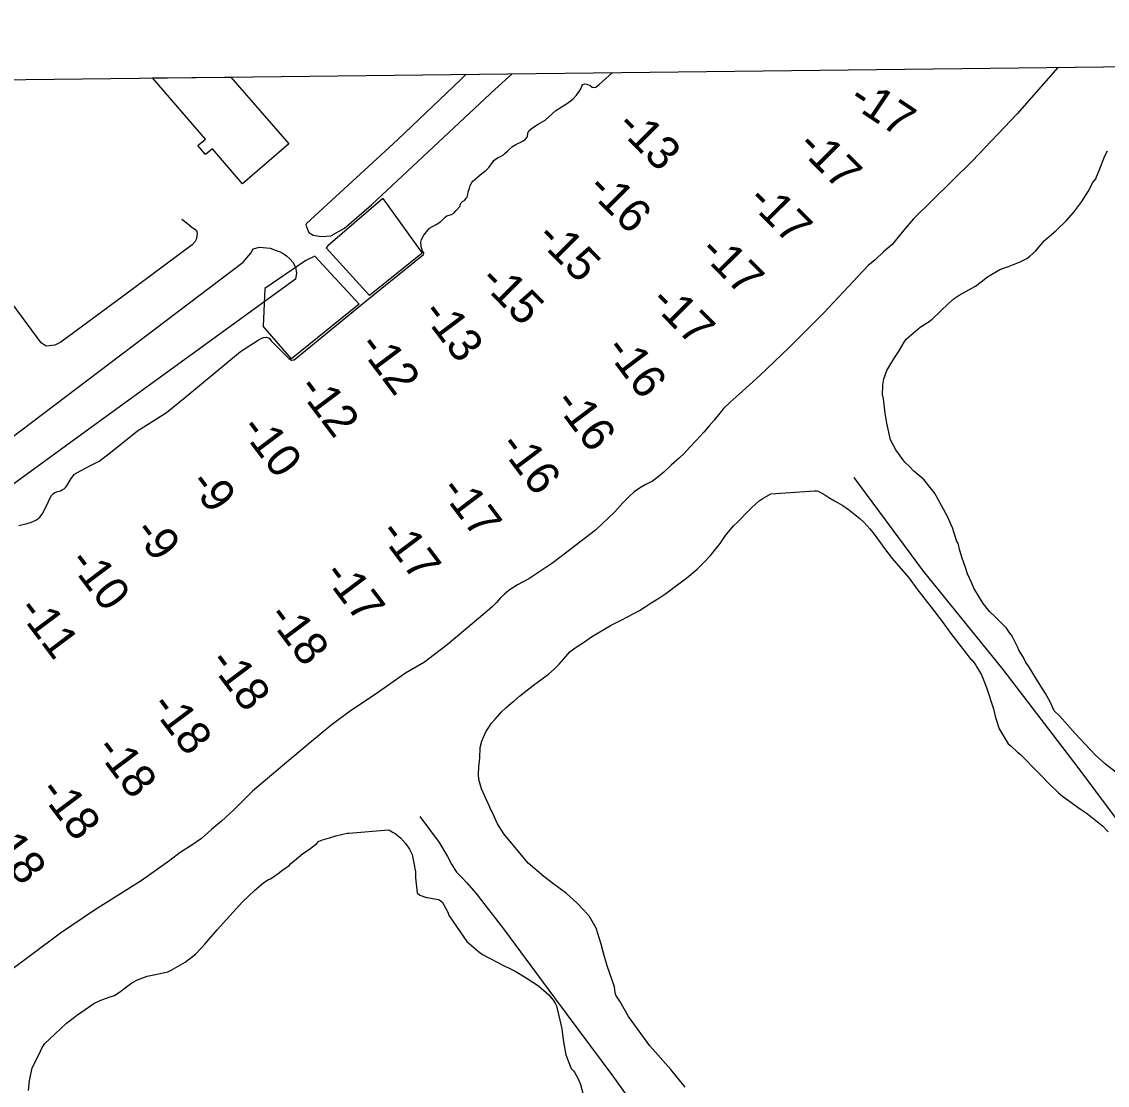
# Model space of a CAD drawing. Extents: x 3683613 to 3738215, y 469626 to 495384.
# Drawn here: x 3695195 to 3696666, y 491946 to 493388 of the extents above; entities that cross this region are included whole.
import ezdxf

# ---------------------------------------------------------------- set-up
doc = ezdxf.new("R2010")
doc.units = 0
for name, color, linetype in [('V-BLDG-OTLN', 7, 'Continuous'), ('V-CHAN-DOCK', 7, 'Continuous'), ('V-GRID-FRAM', 7, 'Continuous'), ('V-LEVE-TOET', 7, 'Continuous'), ('V-SITE-VEGE', 7, 'Continuous'), ('V-TOPO-SHOR', 7, 'Continuous'), ('V-TOPO-SPOT', 7, 'Continuous')]:
    doc.layers.add(name, color=color, linetype=linetype)

msp = doc.modelspace()

# ---------------------------------------------------------------- linework, layer by layer
at = {"layer": 'V-BLDG-OTLN'}
for p, q in [((3695371.7, 493311.7), (3695478.2, 493312.9)), ((3695443.5, 493228.5), (3695371.7, 493311.7)), ((3695478.2, 493312.9), (3695556.5, 493222.4)), ((3695433.5, 493219.9), (3695443.5, 493228.5)), ((3695443.9, 493207.9), (3695433.5, 493219.9)), ((3695453.1, 493215.7), (3695443.9, 493207.9)), ((3695494, 493168.3), (3695453.1, 493215.7)), ((3695556.5, 493222.4), (3695494, 493168.3))]:
    msp.add_line(p, q, dxfattribs=at)
at = {"layer": 'V-CHAN-DOCK'}
for points in [[(3695684.3, 493148.1), (3695609.6, 493083.8), (3695607.5, 493081.5), (3695666.2, 493016.5)], [(3695684.3, 493148.1), (3695737.6, 493074.3), (3695666.2, 493016.5)], [(3695652, 493005), (3695591.8, 493070.1), (3695579.5, 493064.2), (3695524.2, 493026.3), (3695522, 492975.1)], [(3695652, 493005), (3695560.5, 492930.9), (3695522, 492975.1)]]:
    msp.add_lwpolyline(points, dxfattribs=at)
at = {"layer": 'V-GRID-FRAM'}
msp.add_lwpolyline([(3687651.7, 493221.8), (3719350.3, 493590.7), (3719569.8, 475409.4), (3687855.3, 475040.3), (3687651.7, 493221.8)], dxfattribs=at)
at = {"layer": 'V-LEVE-TOET'}
for points in [[(3695797, 493316.6), (3695789.7, 493309.4), (3695703.9, 493227.9), (3695580.8, 493114.5), (3695579.7, 493112), (3695583.8, 493102.1), (3695589.5, 493098.6), (3695600.5, 493096.7), (3695613.6, 493097.7), (3695632.1, 493108.2), (3695668.8, 493139.4), (3695836.4, 493296.6), (3695859.6, 493317.4)], [(3695179.8, 492823.3), (3695494.7, 493061.7), (3695505.1, 493073.9), (3695508.2, 493079.8), (3695516.8, 493082.3), (3695531.5, 493080.8), (3695539.3, 493077.9), (3695544.7, 493076.1), (3695549, 493073.8), (3695553.7, 493070.6), (3695557.9, 493066.5), (3695562.4, 493061.4), (3695565.7, 493054.8), (3695566.9, 493047.3), (3695565.9, 493038.8), (3695280.6, 492831.8), (3695045.1, 492660.8)]]:
    msp.add_lwpolyline(points, dxfattribs=at)
at = {"layer": 'V-SITE-VEGE'}
for points in [[(3696532.4, 492561.6), (3696529.7, 492565.7), (3696513.3, 492581.9), (3696507.1, 492587.7), (3696498.2, 492599.2), (3696485.5, 492620.1), (3696482.1, 492627.8), (3696476.8, 492639.2), (3696473.5, 492649.4), (3696469.4, 492660.7), (3696466.5, 492670.9), (3696464, 492681), (3696462.5, 492683), (3696458.8, 492694.4), (3696456.6, 492701.7), (3696451.7, 492713.1), (3696449.4, 492718), (3696431.9, 492749), (3696424.5, 492758.5), (3696417.9, 492766.7), (3696403.4, 492778.8), (3696398.4, 492784.6), (3696391.7, 492790.8), (3696389, 492794.5), (3696379.8, 492807.6), (3696372.5, 492821.1), (3696367.2, 492843.8), (3696365.1, 492857.1), (3696363.2, 492872.8), (3696362.6, 492879.3), (3696361.4, 492880.9), (3696361.9, 492895.8), (3696363.3, 492903.7), (3696367.3, 492914.9), (3696377, 492930.7), (3696383.3, 492940.5), (3696390.9, 492953.2), (3696393.8, 492957.5), (3696412.8, 492973.8), (3696424.7, 492981.5), (3696428.8, 492984.6), (3696451.1, 493006), (3696458.5, 493012.6), (3696465.5, 493017.3), (3696487.6, 493029.5), (3696495.4, 493035.3), (3696504, 493042.2), (3696520.8, 493051.8), (3696532.5, 493055.9), (3696548.4, 493062.2), (3696557.4, 493066.8), (3696561.5, 493069.9), (3696568.9, 493076.9), (3696581.4, 493091.4), (3696590.5, 493099.5), (3696596.7, 493104.2), (3696611.1, 493118.2), (3696621.1, 493129.6), (3696632, 493144.1), (3696640.4, 493157.9), (3696646.8, 493169.8), (3696650.6, 493174.9), (3696651.5, 493177.7), (3696653.2, 493180.9), (3696655.3, 493186), (3696663.1, 493205.9), (3696666.6, 493213)], [(3696178.8, 492724), (3696183.8, 492729), (3696194.5, 492738.4), (3696198.6, 492741.1), (3696210, 492747.6), (3696269.2, 492751.8), (3696272.4, 492751.7), (3696274.4, 492751.3), (3696283.5, 492746.6), (3696288.6, 492742.8), (3696296.5, 492738.2), (3696307.6, 492732.2), (3696312.7, 492728.4), (3696315.1, 492727.2), (3696330.8, 492714.3), (3696336.3, 492709.3), (3696344.4, 492700.2), (3696350.3, 492693.2), (3696365.7, 492671.8), (3696374.6, 492660.3), (3696397.5, 492633.5), (3696407.9, 492618.8), (3696430.8, 492590), (3696443.9, 492573.1), (3696452.8, 492560.4), (3696457.5, 492554.2), (3696480.3, 492524.6), (3696483, 492522.1), (3696488.1, 492515.5), (3696488.8, 492513.5), (3696495.7, 492502.4), (3696502.4, 492485.4), (3696512, 492456.2), (3696514.9, 492444.8), (3696519.7, 492429), (3696531.9, 492409), (3696535.4, 492406), (3696544.8, 492397.7), (3696548.8, 492394.4), (3696573.3, 492369.2), (3696588.6, 492353.8), (3696599.9, 492343.1), (3696605.8, 492338.1), (3696630.1, 492320.1), (3696639.6, 492313.8), (3696659.6, 492297.9), (3696667.4, 492289.6)], [(3696093.8, 491943.3), (3696074.5, 491967.2), (3696046.1, 491999.4), (3696017.1, 492039.2), (3696005.3, 492060.1), (3695999.9, 492068.3), (3695999.2, 492071.5), (3695998.2, 492079.6), (3695988.2, 492108), (3695983.1, 492125), (3695980.2, 492137.2), (3695973.2, 492159.1), (3695964.1, 492174.6), (3695956.3, 492183.7), (3695947.3, 492193.2), (3695932.9, 492206.1), (3695915.9, 492218.6), (3695902.2, 492229.1), (3695881, 492247), (3695848, 492286.9), (3695839.6, 492300.4), (3695833.2, 492314.3), (3695832.5, 492316.7), (3695830.2, 492320.4), (3695829, 492322.8), (3695818.1, 492347.7), (3695814.1, 492360.7), (3695813.9, 492367.5), (3695814.2, 492378.3), (3695815.7, 492389.5), (3695816.1, 492404), (3695818.4, 492412.4), (3695820.6, 492417.9), (3695823.6, 492425.1), (3695825.7, 492427.8), (3695831.6, 492436.9), (3695836.2, 492442.4), (3695842.8, 492449.4), (3695844.5, 492451.8), (3695850.7, 492457.6), (3695858.1, 492463.8), (3695861.8, 492466.5), (3695869.2, 492473.5), (3695888.6, 492488.6), (3695908.7, 492503.3), (3695916.5, 492509.9), (3695923.2, 492517), (3695929.4, 492524), (3695937.7, 492533.8), (3695944.7, 492539.2), (3695957.4, 492547.3), (3695967.2, 492553.8), (3695992.6, 492569.1), (3696007.3, 492576.7), (3696015.9, 492580.9), (3696032.2, 492589.7), (3696040, 492594.7), (3696047.8, 492600.1), (3696056.8, 492605.4), (3696067.8, 492612.7), (3696075.2, 492618.1), (3696096.2, 492634), (3696110.2, 492645.6), (3696119.3, 492654.6), (3696128.4, 492664.4), (3696141.3, 492680.5), (3696148.9, 492691.1), (3696159.7, 492704.4), (3696165.5, 492709.9), (3696178.8, 492724)], [(3696688.5, 492362.5), (3696664.1, 492381.3), (3696650.4, 492393.4), (3696622.7, 492422.8), (3696602.1, 492446.3), (3696594.3, 492453.7), (3696592.4, 492457.8), (3696589.4, 492464.7), (3696582.5, 492477), (3696576, 492487.2), (3696574.1, 492490.5), (3696560.3, 492512.6), (3696556.1, 492519.1), (3696552.6, 492525.7), (3696546.5, 492535.9), (3696545, 492539.6), (3696537.4, 492554.7), (3696532.4, 492561.6)], [(3695203.7, 491939.1), (3695204.9, 491951.9), (3695208.6, 491969.5), (3695217.6, 491987.3), (3695222.3, 491997.2), (3695225.7, 492002.4), (3695232.3, 492008.6), (3695255.4, 492030), (3695264.1, 492037), (3695268.6, 492040.5), (3695292.4, 492057), (3695300.9, 492060.8), (3695313.1, 492065.3), (3695320.4, 492067.5), (3695329, 492073.6), (3695334.8, 492078.3), (3695343.8, 492084.8), (3695351.6, 492089), (3695364.6, 492093.9), (3695373.5, 492095.6), (3695392.5, 492099.9), (3695397, 492102.2), (3695416.2, 492112.8), (3695430.2, 492123.7), (3695438.9, 492132.7), (3695443, 492137.4), (3695459.3, 492156.6), (3695484.6, 492184.8), (3695493.7, 492194.5), (3695510.3, 492210.1), (3695519.8, 492218.3), (3695523, 492221), (3695529.2, 492224.8), (3695532, 492225.9), (3695542.3, 492233.3), (3695548.5, 492237.9), (3695557.1, 492244.1), (3695559.1, 492246), (3695569.9, 492255.4), (3695575.6, 492260), (3695584.7, 492266.2), (3695594.5, 492273.9), (3695597, 492276.3), (3695599.9, 492277.8), (3695602.3, 492278.9), (3695612, 492281.4), (3695620.5, 492284), (3695635.9, 492287.6), (3695637.9, 492287.9)], [(3695637.9, 492287.9), (3695691.9, 492292.3), (3695694.7, 492291.1), (3695698.2, 492288.5), (3695700.2, 492287.7), (3695708.4, 492281)], [(3695708.4, 492281), (3695715.4, 492273.2), (3695720.1, 492266.2), (3695723.9, 492258.9), (3695728.4, 492235.4), (3695728.5, 492227), (3695730.8, 492206.8), (3695734.3, 492203.9), (3695743.4, 492200.4), (3695747, 492200.3), (3695759.4, 492197.9), (3695764.6, 492194.6), (3695771.8, 492181.5), (3695774, 492175.8), (3695797.9, 492140.9), (3695813.6, 492127.2), (3695819.1, 492123.4), (3695848.8, 492107.7), (3695856.3, 492104.3), (3695863.4, 492100.8), (3695870.1, 492096.6), (3695880, 492090.7), (3695895, 492081), (3695909.1, 492068.5), (3695915.3, 492061.1), (3695918.4, 492056.6), (3695919.5, 492053.8), (3695926.6, 492022.6), (3695928.6, 492007.7), (3695932.4, 491987.1), (3695939.5, 491968.8), (3695942.6, 491965.5), (3695943.8, 491963.9), (3695949.1, 491954.9), (3695952.1, 491947.1), (3695960.1, 491916.4)]]:
    msp.add_lwpolyline(points, dxfattribs=at)
at = {"layer": 'V-TOPO-SHOR'}
for points in [[(3696599.4, 493326), (3696544.3, 493263), (3696483, 493198.9), (3696403.8, 493120.8), (3696390.6, 493105.4), (3696374.6, 493086), (3696363, 493075.7), (3696352, 493065.3), (3696342.3, 493057.2), (3696315.5, 493029), (3696281.5, 492992.7), (3696235.1, 492946), (3696195.1, 492908.3), (3696167.3, 492882.8), (3696155.2, 492872.3), (3696146.1, 492863.6), (3696141, 492857.3), (3696133.3, 492847.8), (3696126.6, 492840), (3696119.2, 492831.5), (3696109.4, 492820.5), (3696100.1, 492810.5), (3696092.5, 492802.3), (3696086.2, 492796.6), (3696075.4, 492787), (3696065.2, 492777.4), (3696057.6, 492770.9), (3696049.8, 492764.9), (3696040.5, 492760.4), (3696032.2, 492755.7), (3696025, 492750.6), (3696017.9, 492744.1), (3696009.5, 492735.6), (3695998.6, 492723.5), (3695972.5, 492698.4), (3695939.4, 492673.4), (3695914.4, 492654.3), (3695882, 492632.6), (3695866.7, 492624.3), (3695855.6, 492617), (3695848.9, 492611.9), (3695843.8, 492606.9), (3695838.1, 492600.7), (3695831.8, 492594.1), (3695823, 492586.5), (3695814, 492578.6), (3695771.4, 492542.9), (3695754.1, 492530), (3695740.6, 492519.7), (3695714.8, 492504.7), (3695673.6, 492475.8), (3695640.5, 492453.5), (3695613.4, 492433.9), (3695587.2, 492412), (3695547.9, 492379.1), (3695507.3, 492344.6), (3695482.1, 492319.4), (3695465.3, 492304.1), (3695452, 492292.9), (3695438.3, 492280.7), (3695425.2, 492271.5), (3695409.5, 492261.5), (3695395.3, 492250.7), (3695356.5, 492223.3), (3695293.4, 492183.2), (3695246.9, 492152.2), (3695207.7, 492122.8), (3695157.8, 492085.6)], [(3695946.8, 493288.1), (3695950.2, 493293.4), (3695952.5, 493296.8), (3695954.1, 493300.3), (3695955.4, 493302.6), (3695957.7, 493303.6), (3695960.9, 493303.2), (3695965, 493301.4), (3695968.1, 493299.1), (3695970.2, 493298.6), (3695973, 493299.3), (3695977.3, 493302.8), (3695995.3, 493318.9)], [(3695332, 493015.8), (3695247.5, 492953.4), (3695239.5, 492949.3), (3695227.6, 492947.9), (3695220.8, 492952.7), (3694981.6, 493276), (3694959.5, 493306.9)], [(3695190.6, 492705), (3695201.8, 492707.5), (3695208, 492709.2), (3695214.7, 492712.6), (3695219, 492716), (3695222.1, 492720.3), (3695226.2, 492728.1), (3695230.9, 492737.6), (3695234.5, 492745.1), (3695237.4, 492748.1), (3695239.6, 492749.7), (3695243.5, 492750.9), (3695247, 492751.8), (3695249.5, 492753.2), (3695251.9, 492754.8), (3695254, 492756.6), (3695255.9, 492758.8), (3695261.7, 492768.7), (3695265.9, 492774.4), (3695274, 492779.2), (3695287.7, 492786.1), (3695299.4, 492792.1), (3695312.8, 492801.9), (3695351.4, 492833), (3695390.6, 492858.2), (3695417.2, 492879.1), (3695491.2, 492940.9), (3695514.9, 492956.3), (3695519, 492958.6), (3695522.1, 492959.8), (3695526.4, 492960.3), (3695529.9, 492958.7), (3695533.3, 492954.9), (3695556.5, 492931.1), (3695560.3, 492929.1), (3695562.4, 492929.3), (3695563.9, 492929.6), (3695661.4, 493009.4), (3695739.2, 493072.3), (3695739.9, 493074.2), (3695739.7, 493075), (3695737.8, 493076.9), (3695736.3, 493083.3), (3695735.6, 493088.9), (3695736.7, 493092.8), (3695739.9, 493098.3), (3695747.4, 493107.9), (3695756.2, 493113), (3695762.7, 493117.2), (3695765.9, 493120.1), (3695768.4, 493122.7), (3695770.9, 493124.7), (3695774, 493125.7), (3695777.2, 493126.6), (3695780.2, 493128.5), (3695783.2, 493131.6), (3695788.7, 493137.5), (3695789.5, 493140.7), (3695790.3, 493142.5), (3695792.3, 493144.3), (3695795.2, 493145.8), (3695797.2, 493148.6), (3695798.3, 493150.1), (3695799.3, 493153.6), (3695800, 493157.3), (3695801.4, 493162.2), (3695802.6, 493165.8), (3695804.8, 493169.9), (3695806.1, 493171.7), (3695812.4, 493177.1), (3695816, 493180.4), (3695824.2, 493186.6), (3695827.7, 493190.2), (3695830.6, 493193.9), (3695832.7, 493197.2), (3695834.8, 493199.6), (3695838.1, 493202.3), (3695840.7, 493203.6), (3695844.7, 493205.7), (3695847.7, 493207.6), (3695850.1, 493209.5), (3695853.2, 493212.4), (3695855.7, 493214.9), (3695859.7, 493218.5), (3695864.3, 493221.3), (3695868.2, 493223.2), (3695870.4, 493224.3), (3695874.3, 493226.2), (3695877.6, 493228.6), (3695879.9, 493231.3), (3695880.2, 493232.2), (3695880.8, 493236.8), (3695882.2, 493239.8), (3695886.9, 493243.8), (3695894.7, 493248.8), (3695904, 493254.5), (3695918.8, 493267.4), (3695934.4, 493277.5), (3695941.7, 493282.8), (3695946.8, 493288.1)], [(3695411.4, 493120.2), (3695419.4, 493114.4), (3695425.3, 493109.3), (3695429.9, 493106.3), (3695431.8, 493103.5), (3695432.3, 493100.5), (3695432, 493097), (3695431.1, 493092.8), (3695429.8, 493090.1), (3695425.8, 493085.3), (3695332, 493015.8)], [(3696322.9, 492769.8), (3696416.6, 492643.1), (3696524.5, 492509.8), (3696626.2, 492377), (3696791.4, 492155.8), (3696888.5, 492024.4), (3696918.4, 491987.4), (3696928.5, 491973.1)], [(3695734.3, 492310.3), (3695760.7, 492275.2), (3695771.7, 492256.2), (3695777.4, 492245.6), (3695783.8, 492235), (3695791.1, 492227.5), (3695797.8, 492220.3), (3695810.3, 492206.6), (3695847.9, 492157.9), (3695916.9, 492064.6), (3695996.1, 491958.4), (3696088.9, 491828), (3696187.1, 491698.1), (3696290, 491557.9), (3696302.4, 491539.1), (3696310.5, 491524.7), (3696317.1, 491513.9), (3696324.5, 491502.9), (3696330.1, 491496.4), (3696335.9, 491489.6), (3696342.4, 491481.3), (3696349.4, 491472.7), (3696358.2, 491462.9), (3696366.6, 491453.2)]]:
    msp.add_lwpolyline(points, dxfattribs=at)

# ---------------------------------------------------------------- texts
at = {"layer": 'V-TOPO-SPOT'}
for s, rotation, p in [('-17', 326.2505, (3696313.6, 493277.2)), ('-13', 314.8368, (3695998.8, 493244.5)), ('-17', 314.8368, (3696244, 493217.5)), ('-16', 314.8368, (3695959, 493159.8)), ('-17', 314.8368, (3696176.6, 493144)), ('-15', 314.8368, (3695890.2, 493093.4)), ('-17', 314.8368, (3696111.3, 493074.6)), ('-15', 314.8368, (3695813.3, 493035)), ('-17', 314.8368, (3696044.7, 493006.5)), ('-13', 306.9347, (3695735.4, 492992.4)), ('-12', 306.9347, (3695649.3, 492947.8)), ('-16', 306.9347, (3695983.8, 492943.4)), ('-12', 306.9347, (3695567, 492890.5)), ('-16', 306.9347, (3695914.8, 492871.4)), ('-10', 306.9347, (3695489.3, 492835.8)), ('-16', 306.9347, (3695840.2, 492812.5)), ('-9', 306.9347, (3695420.1, 492761.6)), ('-17', 306.9347, (3695760.1, 492752.7)), ('-9', 306.9347, (3695344.6, 492696.1)), ('-17', 306.9347, (3695677.6, 492694.4)), ('-10', 306.9347, (3695256.5, 492655.2)), ('-17', 306.9347, (3695601.6, 492638.1)), ('-11', 306.9347, (3695187, 492590)), ('-18', 306.9347, (3695526.1, 492581)), ('-18', 306.9347, (3695446.7, 492519.3)), ('-18', 306.9347, (3695367.6, 492459.8)), ('-18', 306.9347, (3695292.7, 492401.4)), ('-18', 306.9347, (3695216.4, 492344.2)), ('-18', 306.9347, (3695142.8, 492284.2))]:
    msp.add_text(s, height=45, rotation=rotation, dxfattribs=at).set_placement(p)

doc.saveas('drawing.dxf')
